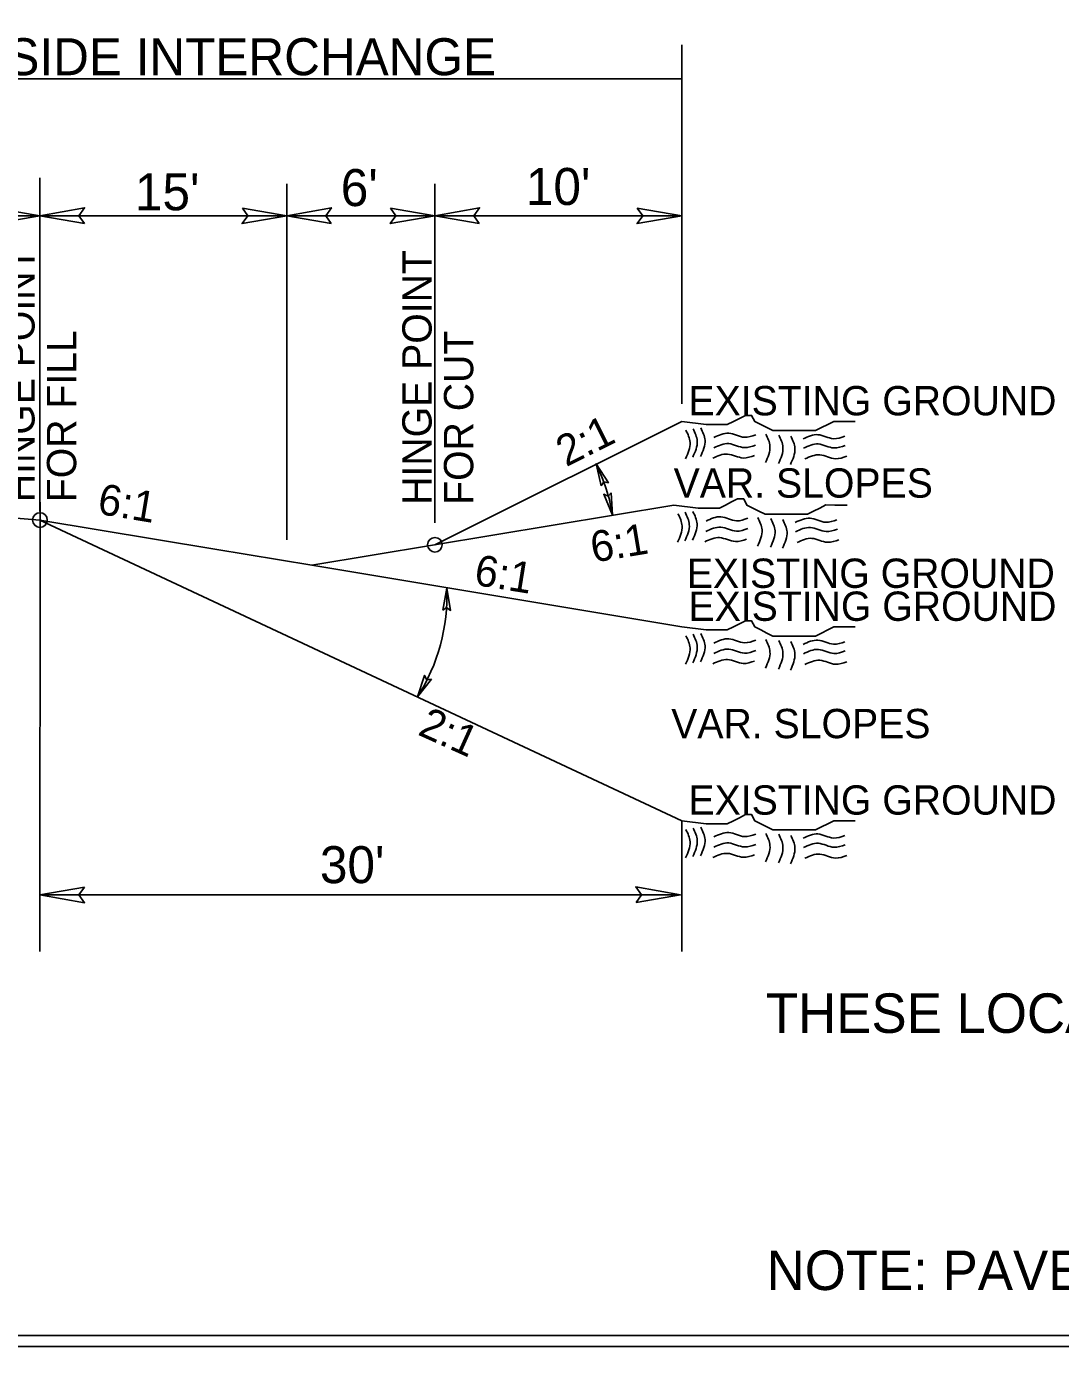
# Model space of a CAD drawing. Extents: x 573813 to 575363, y -54752 to -53123.
# Drawn here: x 574880.5 to 574928.2, y -53558.6 to -53497.7 of the extents above; entities that cross this region are included whole.
import ezdxf

# ---------------------------------------------------------------- set-up
doc = ezdxf.new("R2010")
doc.units = 0
for name, color, linetype in [('Old_Level_1', 7, 'Continuous'), ('Old_Level_11', 7, 'Continuous'), ('Old_Level_2', 7, 'Continuous'), ('Sheet Plot Border Inside CELL', 7, 'Continuous'), ('Sheet Typical CELL', 7, 'Continuous')]:
    doc.layers.add(name, color=color, linetype=linetype)

msp = doc.modelspace()

# ---------------------------------------------------------------- linework, layer by layer
at = {"layer": 'Old_Level_1'}
for p, q in [((574910.722, -53515.944), (574900.427, -53521.095)), ((574872.12, -53519.765), (574881.161, -53520.488)), ((574910.357, -53519.795), (574893.68, -53522.574)), ((574889.209, -53521.829), (574881.161, -53520.488)), ((574881.161, -53520.488), (574910.723, -53534.346)), ((574900.427, -53521.095), (574899.352, -53521.629)), ((574893.68, -53522.574), (574889.209, -53521.829)), ((574910.723, -53525.415), (574893.68, -53522.574))]:
    msp.add_line(p, q, dxfattribs=at)
for points in [[(574910.722, -53515.944), (574911.842, -53516.084), (574912.123, -53516.083), (574912.543, -53516.083), (574912.823, -53516.083), (574913.103, -53515.944), (574913.384, -53515.803), (574913.664, -53515.663), (574913.944, -53515.663), (574914.085, -53515.944), (574914.365, -53516.083), (574914.645, -53516.224), (574914.925, -53516.363), (574915.205, -53516.364), (574915.486, -53516.364), (574915.766, -53516.364), (574916.046, -53516.364), (574916.326, -53516.364), (574916.606, -53516.364), (574916.886, -53516.364), (574917.167, -53516.224), (574917.447, -53516.083), (574917.727, -53515.944), (574918.148, -53515.944), (574918.428, -53515.944), (574918.708, -53515.944)], [(574910.357, -53519.795), (574911.477, -53519.934), (574911.757, -53519.934), (574912.178, -53519.934), (574912.458, -53519.934), (574912.738, -53519.795), (574913.019, -53519.654), (574913.299, -53519.513), (574913.579, -53519.513), (574913.72, -53519.795), (574914, -53519.934), (574914.28, -53520.075), (574914.56, -53520.214), (574914.84, -53520.214), (574915.121, -53520.214), (574915.4, -53520.214), (574915.681, -53520.214), (574915.961, -53520.214), (574916.241, -53520.214), (574916.521, -53520.214), (574916.801, -53520.075), (574917.082, -53519.934), (574917.362, -53519.794), (574917.782, -53519.795), (574918.063, -53519.795), (574918.343, -53519.795)], [(574910.723, -53525.415), (574911.843, -53525.554), (574912.123, -53525.554), (574912.544, -53525.554), (574912.824, -53525.554), (574913.104, -53525.415), (574913.385, -53525.274), (574913.665, -53525.134), (574913.945, -53525.133), (574914.086, -53525.415), (574914.366, -53525.554), (574914.646, -53525.695), (574914.926, -53525.834), (574915.206, -53525.835), (574915.486, -53525.835), (574915.766, -53525.835), (574916.047, -53525.835), (574916.327, -53525.835), (574916.607, -53525.835), (574916.887, -53525.834), (574917.167, -53525.695), (574917.448, -53525.554), (574917.728, -53525.415), (574918.148, -53525.415), (574918.428, -53525.415), (574918.709, -53525.415)], [(574910.723, -53534.346), (574911.843, -53534.485), (574912.123, -53534.485), (574912.544, -53534.485), (574912.824, -53534.485), (574913.104, -53534.346), (574913.385, -53534.205), (574913.665, -53534.064), (574913.945, -53534.064), (574914.086, -53534.345), (574914.366, -53534.485), (574914.646, -53534.626), (574914.926, -53534.765), (574915.206, -53534.765), (574915.487, -53534.765), (574915.767, -53534.765), (574916.047, -53534.765), (574916.327, -53534.765), (574916.607, -53534.765), (574916.887, -53534.765), (574917.168, -53534.626), (574917.448, -53534.485), (574917.728, -53534.345), (574918.148, -53534.346), (574918.429, -53534.346), (574918.709, -53534.346)]]:
    msp.add_lwpolyline(points, dxfattribs=at)
for centre in [(574881.161, -53520.488), (574881.161, -53520.488), (574899.352, -53521.629)]:
    msp.add_circle(centre, 0.338, dxfattribs=at)
for centre, start, end in [((574898.872, -53521.763), 9.81225, 26.06657), ((574891.108, -53523.955), 327.81896, 2.17637)]:
    msp.add_arc(centre, 8.798, start, end, dxfattribs=at)
at = {"layer": 'Old_Level_11'}
for p, q in [((574910.722, -53515.126), (574910.722, -53498.594)), ((574910.722, -53500.155), (574867.517, -53500.153)), ((574881.161, -53520.087), (574881.161, -53504.722)), ((574892.531, -53521.399), (574892.531, -53504.998)), ((574899.353, -53520.623), (574899.352, -53504.998)), ((574881.161, -53506.463), (574867.517, -53506.463)), ((574881.106, -53506.463), (574892.476, -53506.464)), ((574892.476, -53506.464), (574899.298, -53506.463)), ((574899.297, -53506.463), (574910.722, -53506.464)), ((574881.161, -53540.374), (574881.162, -53519.666)), ((574910.723, -53540.375), (574910.723, -53534.348)), ((574881.161, -53537.76), (574910.667, -53537.761))]:
    msp.add_line(p, q, dxfattribs=at)
for points in [[(574879.115, -53506.111), (574881.161, -53506.463), (574879.103, -53506.827), (574879.365, -53506.463)], [(574883.208, -53506.816), (574881.161, -53506.463), (574883.219, -53506.099), (574882.958, -53506.463)], [(574890.484, -53506.111), (574892.531, -53506.464), (574890.473, -53506.827), (574890.734, -53506.464)], [(574894.577, -53506.816), (574892.531, -53506.464), (574894.589, -53506.1), (574894.327, -53506.464)], [(574897.306, -53506.111), (574899.352, -53506.463), (574897.295, -53506.827), (574897.556, -53506.464)], [(574901.399, -53506.816), (574899.352, -53506.463), (574901.41, -53506.1), (574901.149, -53506.463)], [(574908.676, -53506.111), (574910.722, -53506.464), (574908.664, -53506.827), (574908.926, -53506.464)], [(574907.019, -53518.906), (574906.775, -53517.897), (574907.35, -53518.77), (574907.131, -53518.722)], [(574907.481, -53519.227), (574907.542, -53520.264), (574907.131, -53519.303), (574907.337, -53519.389)], [(574899.716, -53524.643), (574899.899, -53523.621), (574900.074, -53524.652), (574899.893, -53524.519)], [(574899.193, -53527.823), (574898.554, -53528.641), (574898.881, -53527.649), (574898.979, -53527.85)], [(574883.208, -53537.408), (574881.161, -53537.76), (574883.219, -53538.124), (574882.958, -53537.76)], [(574908.621, -53538.113), (574910.667, -53537.761), (574908.609, -53537.397), (574908.871, -53537.761)]]:
    msp.add_lwpolyline(points, close=True, dxfattribs=at)
at = {"layer": 'Old_Level_2'}
for points in [[(574911.603, -53516.245), (574911.797, -53516.81), (574911.589, -53517.558)], [(574911.603, -53516.245), (574911.797, -53516.81), (574911.589, -53517.558)], [(574910.917, -53516.346), (574911.109, -53516.91), (574910.902, -53517.66)], [(574910.917, -53516.346), (574911.109, -53516.91), (574910.902, -53517.66)], [(574911.249, -53516.282), (574911.439, -53516.848), (574911.232, -53517.597)], [(574911.249, -53516.282), (574911.439, -53516.848), (574911.232, -53517.597)], [(574912.207, -53516.685), (574912.889, -53516.488), (574913.615, -53516.673), (574914.133, -53516.556)], [(574912.207, -53516.685), (574912.889, -53516.488), (574913.615, -53516.673), (574914.133, -53516.556)], [(574914.599, -53516.524), (574914.789, -53517.088), (574914.585, -53517.837)], [(574914.599, -53516.524), (574914.789, -53517.088), (574914.585, -53517.837)], [(574915.195, -53516.57), (574915.387, -53517.135), (574915.182, -53517.885)], [(574915.195, -53516.57), (574915.387, -53517.135), (574915.182, -53517.885)], [(574915.747, -53516.619), (574915.939, -53517.185), (574915.731, -53517.932)], [(574915.747, -53516.619), (574915.939, -53517.185), (574915.731, -53517.932)], [(574916.312, -53516.75), (574916.998, -53516.554), (574917.718, -53516.739), (574918.241, -53516.624)], [(574916.312, -53516.75), (574916.998, -53516.554), (574917.718, -53516.739), (574918.241, -53516.624)], [(574912.15, -53517.641), (574912.834, -53517.448), (574913.56, -53517.629), (574914.08, -53517.513)], [(574912.15, -53517.641), (574912.834, -53517.448), (574913.56, -53517.629), (574914.08, -53517.513)], [(574912.203, -53517.161), (574912.889, -53516.967), (574913.609, -53517.152), (574914.129, -53517.034)], [(574912.203, -53517.161), (574912.889, -53516.967), (574913.609, -53517.152), (574914.129, -53517.034)], [(574916.33, -53517.179), (574917.016, -53516.982), (574917.736, -53517.168), (574918.259, -53517.051)], [(574916.33, -53517.179), (574917.016, -53516.982), (574917.736, -53517.168), (574918.259, -53517.051)], [(574916.4, -53517.675), (574917.084, -53517.48), (574917.808, -53517.664), (574918.328, -53517.547)], [(574916.4, -53517.675), (574917.084, -53517.48), (574917.808, -53517.664), (574918.328, -53517.547)], [(574910.552, -53520.197), (574910.744, -53520.761), (574910.536, -53521.51)], [(574910.552, -53520.197), (574910.744, -53520.761), (574910.536, -53521.51)], [(574910.884, -53520.132), (574911.074, -53520.698), (574910.866, -53521.448)], [(574910.884, -53520.132), (574911.074, -53520.698), (574910.866, -53521.448)], [(574911.238, -53520.095), (574911.432, -53520.661), (574911.224, -53521.408)], [(574911.238, -53520.095), (574911.432, -53520.661), (574911.224, -53521.408)], [(574911.842, -53520.536), (574912.524, -53520.339), (574913.25, -53520.524), (574913.768, -53520.406)], [(574911.842, -53520.536), (574912.524, -53520.339), (574913.25, -53520.524), (574913.768, -53520.406)], [(574914.233, -53520.375), (574914.424, -53520.938), (574914.22, -53521.688)], [(574914.233, -53520.375), (574914.424, -53520.938), (574914.22, -53521.688)], [(574914.83, -53520.42), (574915.022, -53520.986), (574914.816, -53521.736)], [(574914.83, -53520.42), (574915.022, -53520.986), (574914.816, -53521.736)], [(574915.382, -53520.47), (574915.574, -53521.036), (574915.366, -53521.783)], [(574915.382, -53520.47), (574915.574, -53521.036), (574915.366, -53521.783)], [(574915.947, -53520.6), (574916.633, -53520.405), (574917.353, -53520.59), (574917.875, -53520.474)], [(574915.947, -53520.6), (574916.633, -53520.405), (574917.353, -53520.59), (574917.875, -53520.474)], [(574911.838, -53521.011), (574912.524, -53520.818), (574913.244, -53521.003), (574913.764, -53520.885)], [(574911.838, -53521.011), (574912.524, -53520.818), (574913.244, -53521.003), (574913.764, -53520.885)], [(574915.965, -53521.03), (574916.651, -53520.832), (574917.371, -53521.019), (574917.893, -53520.902)], [(574915.965, -53521.03), (574916.651, -53520.832), (574917.371, -53521.019), (574917.893, -53520.902)], [(574911.785, -53521.492), (574912.469, -53521.299), (574913.195, -53521.479), (574913.715, -53521.364)], [(574911.785, -53521.492), (574912.469, -53521.299), (574913.195, -53521.479), (574913.715, -53521.364)], [(574916.035, -53521.526), (574916.719, -53521.331), (574917.442, -53521.515), (574917.963, -53521.398)], [(574916.035, -53521.526), (574916.719, -53521.331), (574917.442, -53521.515), (574917.963, -53521.398)], [(574910.918, -53525.817), (574911.11, -53526.381), (574910.902, -53527.131)], [(574910.918, -53525.817), (574911.11, -53526.381), (574910.902, -53527.131)], [(574911.25, -53525.753), (574911.44, -53526.319), (574911.232, -53527.068)], [(574911.25, -53525.753), (574911.44, -53526.319), (574911.232, -53527.068)], [(574911.603, -53525.716), (574911.798, -53526.281), (574911.59, -53527.029)], [(574911.603, -53525.716), (574911.798, -53526.281), (574911.59, -53527.029)], [(574912.208, -53526.156), (574912.89, -53525.959), (574913.616, -53526.144), (574914.134, -53526.026)], [(574912.208, -53526.156), (574912.89, -53525.959), (574913.616, -53526.144), (574914.134, -53526.026)], [(574914.599, -53525.995), (574914.79, -53526.559), (574914.586, -53527.308)], [(574914.599, -53525.995), (574914.79, -53526.559), (574914.586, -53527.308)], [(574912.204, -53526.632), (574912.89, -53526.438), (574913.61, -53526.623), (574914.13, -53526.505)], [(574912.204, -53526.632), (574912.89, -53526.438), (574913.61, -53526.623), (574914.13, -53526.505)], [(574915.196, -53526.041), (574915.388, -53526.606), (574915.182, -53527.356)], [(574915.196, -53526.041), (574915.388, -53526.606), (574915.182, -53527.356)], [(574915.748, -53526.09), (574915.94, -53526.656), (574915.732, -53527.403)], [(574915.748, -53526.09), (574915.94, -53526.656), (574915.732, -53527.403)], [(574916.313, -53526.221), (574916.999, -53526.025), (574917.719, -53526.21), (574918.241, -53526.095)], [(574916.313, -53526.221), (574916.999, -53526.025), (574917.719, -53526.21), (574918.241, -53526.095)], [(574916.331, -53526.65), (574917.017, -53526.453), (574917.737, -53526.639), (574918.259, -53526.522)], [(574916.331, -53526.65), (574917.017, -53526.453), (574917.737, -53526.639), (574918.259, -53526.522)], [(574912.151, -53527.112), (574912.835, -53526.919), (574913.561, -53527.1), (574914.081, -53526.984)], [(574912.151, -53527.112), (574912.835, -53526.919), (574913.561, -53527.1), (574914.081, -53526.984)], [(574916.401, -53527.146), (574917.084, -53526.951), (574917.808, -53527.135), (574918.329, -53527.018)], [(574916.401, -53527.146), (574917.084, -53526.951), (574917.808, -53527.135), (574918.329, -53527.018)], [(574910.918, -53534.748), (574911.11, -53535.312), (574910.903, -53536.061)], [(574910.918, -53534.748), (574911.11, -53535.312), (574910.903, -53536.061)], [(574911.25, -53534.683), (574911.44, -53535.249), (574911.233, -53535.999)], [(574911.25, -53534.683), (574911.44, -53535.249), (574911.233, -53535.999)], [(574911.604, -53534.646), (574911.798, -53535.212), (574911.59, -53535.959)], [(574911.604, -53534.646), (574911.798, -53535.212), (574911.59, -53535.959)], [(574912.208, -53535.087), (574912.89, -53534.89), (574913.616, -53535.075), (574914.134, -53534.957)], [(574912.208, -53535.087), (574912.89, -53534.89), (574913.616, -53535.075), (574914.134, -53534.957)], [(574914.6, -53534.926), (574914.79, -53535.489), (574914.586, -53536.239)], [(574914.6, -53534.926), (574914.79, -53535.489), (574914.586, -53536.239)], [(574915.196, -53534.971), (574915.388, -53535.537), (574915.182, -53536.287)], [(574915.196, -53534.971), (574915.388, -53535.537), (574915.182, -53536.287)], [(574915.748, -53535.021), (574915.94, -53535.587), (574915.732, -53536.334)], [(574915.748, -53535.021), (574915.94, -53535.587), (574915.732, -53536.334)], [(574916.313, -53535.151), (574916.999, -53534.956), (574917.719, -53535.141), (574918.241, -53535.025)], [(574916.313, -53535.151), (574916.999, -53534.956), (574917.719, -53535.141), (574918.241, -53535.025)], [(574912.204, -53535.562), (574912.89, -53535.369), (574913.61, -53535.554), (574914.13, -53535.436)], [(574912.204, -53535.562), (574912.89, -53535.369), (574913.61, -53535.554), (574914.13, -53535.436)], [(574916.331, -53535.581), (574917.017, -53535.383), (574917.737, -53535.57), (574918.259, -53535.453)], [(574916.331, -53535.581), (574917.017, -53535.383), (574917.737, -53535.57), (574918.259, -53535.453)], [(574912.151, -53536.043), (574912.835, -53535.85), (574913.561, -53536.03), (574914.081, -53535.915)], [(574912.151, -53536.043), (574912.835, -53535.85), (574913.561, -53536.03), (574914.081, -53535.915)], [(574916.401, -53536.077), (574917.085, -53535.882), (574917.808, -53536.066), (574918.329, -53535.949)], [(574916.401, -53536.077), (574917.085, -53535.882), (574917.808, -53536.066), (574918.329, -53535.949)]]:
    msp.add_spline(points, degree=3, dxfattribs=at)
at = {"layer": 'Sheet Plot Border Inside CELL'}
msp.add_lwpolyline([(575005.811, -53347.445), (574672.332, -53347.445), (574672.332, -53558.578), (575005.811, -53558.578)], close=True, dxfattribs=at)
at = {"layer": 'Sheet Typical CELL'}
msp.add_lwpolyline([(575003.31, -53347.955), (574703.149, -53347.955), (574703.149, -53558.068), (575003.31, -53558.068)], close=True, dxfattribs=at)

# ---------------------------------------------------------------- texts
at = {"layer": 'Old_Level_1'}
for s, height, rotation, p in [('HINGE POINT', 1.35016, 90.00004, (574880.911, -53519.666)), ('HINGE POINT', 1.35016, 90.00004, (574899.202, -53519.787)), ('FOR FILL', 1.3502, 90.00004, (574882.83, -53519.666)), ('FOR CUT ', 1.3502, 90.00004, (574901.12, -53519.787)), ('EXISTING GROUND', 1.35016, 359.99996, (574911.034, -53515.663)), ('2:1', 1.4212, 26.56501, (574905.4, -53518.057)), ('VAR. SLOPES', 1.35016, 359.99996, (574910.351, -53519.456)), ('6:1', 1.4212, 350.53764, (574883.761, -53520.19)), ('6:1', 1.4212, 9.46236, (574906.648, -53522.452)), ('6:1', 1.4212, 350.85277, (574901.114, -53523.467)), ('EXISTING GROUND', 1.35016, 359.99996, (574910.959, -53523.614)), ('EXISTING GROUND', 1.35016, 359.99996, (574911.035, -53525.133)), ('2:1', 1.4212, 335.75757, (574898.514, -53530.36)), ('VAR. SLOPES', 1.35016, 359.99996, (574910.24, -53530.541)), ('EXISTING GROUND', 1.35016, 359.99996, (574911.035, -53534.064)), ('THESE LOCATIONS TO BE INVESTIGATED DURING CONSTRUCTION:', 1.81916, 359.99996, (574914.597, -53544.121)), ('NOTE: PAVE TO THE FACE OF GUARDRAIL ON ALL TYPICAL SECTIONS', 1.81916, 359.99996, (574914.631, -53555.972))]:
    msp.add_text(s, height=height, rotation=rotation, dxfattribs=at).set_placement(p)
at = {"layer": 'Old_Level_11'}
for s, height, rotation, p in [('OUTSIDE INTERCHANGE', 1.70546, 0.00004, (574874.798, -53499.99)), ("15'", 1.7055, 359.99996, (574885.535, -53506.213)), ("6'", 1.7055, 359.99996, (574895.018, -53506.02)), ("10'", 1.7055, 359.99996, (574903.545, -53505.969)), ("30'", 1.7055, 0.00004, (574894.056, -53537.222))]:
    msp.add_text(s, height=height, rotation=rotation, dxfattribs=at).set_placement(p)

doc.saveas('drawing.dxf')
